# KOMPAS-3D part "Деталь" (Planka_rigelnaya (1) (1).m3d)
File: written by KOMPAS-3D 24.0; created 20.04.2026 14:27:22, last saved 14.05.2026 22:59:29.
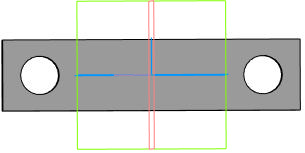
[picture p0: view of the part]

Document properties: Автор: TMK; Полное имя файла: E:\test_kompas\all_v22\Planka_rigelnaya (1) (1).m3d; Организация: TMK

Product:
- Part/product: Деталь
    Масса: 0.134151

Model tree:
1. Эскиз:1
2. Элемент выдавливания:1
     Расстояние 2 = 8
3. Эскиз:2
4. Элемент выдавливания:2
     Расстояние 2 = 10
